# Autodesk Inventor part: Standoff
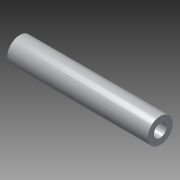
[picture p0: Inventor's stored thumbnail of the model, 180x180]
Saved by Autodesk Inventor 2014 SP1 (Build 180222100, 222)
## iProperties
Created: 2014-07
Part Number: Standoff
Material: Aluminum 6061
Document SubType Name: Modeling
Designer: Admin
Density: 2.71 g/cm^3
Appearance: Aluminum - Flat
Author: Admin
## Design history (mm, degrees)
sketch "Sketch1"
  geometry: C1 r 3.175 at (0, 0); C2 r 6.223 at (0, 0); 1 further point
  constraints: 2 centre point, 2 coincident
  dimensions: "d0" = 6.35 diameter of C1; "d1" = 12.446 diameter of C2
extrude "Extrusion1" new body sketch "Sketch1" distance "d2" = 69.85; taper "d3" = 0 deg
body "Solid1"
